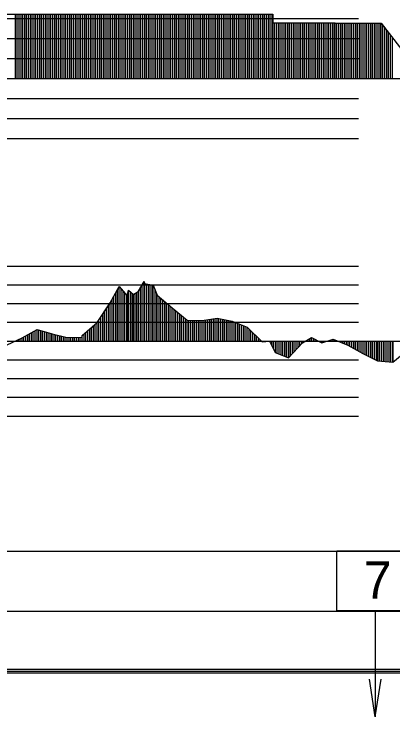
# Model space of a CAD drawing. Extents: x 2 to 10148, y 0 to 380.
# Drawn here: x 3622 to 3672.6, y 191.9 to 285.6 of the extents above; entities that cross this region are included whole.
import ezdxf

# ---------------------------------------------------------------- set-up
doc = ezdxf.new("R2010")
doc.units = 0
for name, color, linetype in [('POSUN_CARA', 7, 'Continuous'), ('POSUN_RASTR', 7, 'Continuous'), ('RYCHL_RASTR', 7, 'Continuous'), ('SLOUPEC', 7, 'Continuous'), ('ZRYCHL_CARA', 7, 'Continuous'), ('ZRYCHL_RASTR', 7, 'Continuous')]:
    doc.layers.add(name, color=color, linetype=linetype)

msp = doc.modelspace()

# ---------------------------------------------------------------- linework, layer by layer
at = {"layer": 'POSUN_CARA'}
for p, q in [((3638.631, 248.668), (3639.39, 249.956)), ((3639.131, 242), (3639.131, 249.517)), ((3639.381, 242), (3639.381, 249.942)), ((3639.39, 249.956), (3639.446, 249.679)), ((3639.39, 242), (3639.39, 249.956)), ((3639.446, 249.679), (3640.584, 249.465)), ((3639.446, 242), (3639.446, 249.679)), ((3639.696, 242), (3639.696, 249.632)), ((3639.946, 242), (3639.946, 249.585)), ((3640.196, 242), (3640.196, 249.538)), ((3640.446, 242), (3640.446, 249.491)), ((3640.584, 249.465), (3641.12, 248.129)), ((3640.584, 242), (3640.584, 249.465)), ((3634.848, 247.075), (3636.067, 249.276)), ((3635.598, 242), (3635.598, 248.429)), ((3635.848, 242), (3635.848, 248.88)), ((3636.067, 249.276), (3637.129, 248.042)), ((3636.067, 242), (3636.067, 249.276)), ((3636.317, 242), (3636.317, 248.986)), ((3636.567, 242), (3636.567, 248.695)), ((3636.817, 242), (3636.817, 248.405)), ((3637.129, 248.042), (3637.304, 248.785)), ((3637.304, 248.785), (3637.95, 248.221)), ((3637.304, 242), (3637.304, 248.785)), ((3637.554, 242), (3637.554, 248.567)), ((3637.804, 242), (3637.804, 248.349)), ((3637.95, 248.221), (3638.631, 248.668)), ((3638.2, 242), (3638.2, 248.385)), ((3638.394, 242), (3638.4, 248.516)), ((3638.631, 242), (3638.631, 248.668)), ((3638.881, 242), (3638.881, 249.093)), ((3640.834, 242), (3640.834, 248.842)), ((3635.098, 242), (3635.098, 247.526)), ((3635.348, 242), (3635.348, 247.977)), ((3637.067, 242), (3637.067, 248.114)), ((3637.129, 242), (3637.129, 248.042)), ((3637.95, 242), (3637.95, 248.221)), ((3641.084, 242), (3641.084, 248.219)), ((3641.12, 248.129), (3643.129, 246.413)), ((3641.12, 242), (3641.12, 248.129)), ((3641.37, 242), (3641.37, 247.916)), ((3641.62, 242), (3641.62, 247.702)), ((3641.87, 242), (3641.87, 247.489)), ((3633.105, 244.463), (3634.848, 247.075)), ((3634.605, 242), (3634.605, 246.711)), ((3634.848, 242), (3634.848, 247.075)), ((3642.12, 242), (3642.12, 247.275)), ((3642.37, 242), (3642.37, 247.062)), ((3642.62, 242), (3642.62, 246.848)), ((3642.87, 242), (3642.87, 246.634)), ((3633.855, 242), (3633.855, 245.587)), ((3634.105, 242), (3634.105, 245.961)), ((3634.355, 242), (3634.355, 246.336)), ((3643.12, 242), (3643.12, 246.421)), ((3643.129, 246.413), (3645.115, 244.77)), ((3643.129, 242), (3643.129, 246.413)), ((3643.379, 242), (3643.379, 246.206)), ((3643.629, 242), (3643.629, 245.999)), ((3643.879, 242), (3643.879, 245.792)), ((3644.129, 242), (3644.129, 245.585)), ((3633.355, 242), (3633.355, 244.837)), ((3633.605, 242), (3633.605, 245.212)), ((3644.379, 242), (3644.379, 245.379)), ((3644.629, 242), (3644.629, 245.172)), ((3644.879, 242), (3644.879, 244.965)), ((3645.115, 244.77), (3647.127, 244.736)), ((3645.115, 242), (3645.115, 244.77)), ((3645.365, 242), (3645.365, 244.766)), ((3645.615, 242), (3645.615, 244.762)), ((3645.865, 242), (3645.865, 244.758)), ((3646.115, 242), (3646.115, 244.753)), ((3646.365, 242), (3646.365, 244.749)), ((3646.615, 242), (3646.615, 244.745)), ((3646.865, 242), (3646.865, 244.741)), ((3647.115, 242), (3647.115, 244.736)), ((3647.127, 244.736), (3649.111, 245.038)), ((3647.127, 242), (3647.127, 244.736)), ((3647.377, 242), (3647.377, 244.774)), ((3647.627, 242), (3647.627, 244.812)), ((3647.877, 242), (3647.877, 244.85)), ((3648.127, 242), (3648.127, 244.889)), ((3648.377, 242), (3648.377, 244.927)), ((3648.627, 242), (3648.627, 244.965)), ((3648.877, 242), (3648.877, 245.003)), ((3649.111, 245.038), (3651.121, 244.656)), ((3649.111, 242), (3649.111, 245.038)), ((3649.361, 242), (3649.361, 244.991)), ((3649.611, 242), (3649.611, 244.943)), ((3649.861, 242), (3649.861, 244.896)), ((3650.111, 242), (3650.111, 244.848)), ((3650.361, 242), (3650.361, 244.8)), ((3650.611, 242), (3650.611, 244.753)), ((3650.861, 242), (3650.861, 244.705)), ((3651.111, 242), (3651.111, 244.658)), ((3651.121, 244.656), (3653.128, 243.837)), ((3651.121, 242), (3651.121, 244.656)), ((3631.116, 242.725), (3633.105, 244.463)), ((3632.366, 242), (3632.366, 243.817)), ((3632.616, 242), (3632.616, 244.036)), ((3632.866, 242), (3632.866, 244.254)), ((3633.105, 242), (3633.105, 244.463)), ((3651.371, 242), (3651.371, 244.554)), ((3651.621, 242), (3651.621, 244.452)), ((3651.871, 242), (3651.871, 244.35)), ((3652.121, 242), (3652.121, 244.248)), ((3652.371, 242), (3652.371, 244.146)), ((3652.621, 242), (3652.621, 244.044)), ((3652.871, 242), (3652.871, 243.942)), ((3653.121, 242), (3653.121, 243.84)), ((3653.128, 243.837), (3655.125, 241.916)), ((3653.128, 242), (3653.128, 243.837)), ((3623.098, 242.411), (3625.089, 243.532)), ((3623.848, 242), (3623.848, 242.833)), ((3624.098, 242), (3624.098, 242.974)), ((3624.348, 242), (3624.348, 243.115)), ((3624.598, 242), (3624.598, 243.256)), ((3624.848, 242), (3624.848, 243.396)), ((3625.089, 243.532), (3627.116, 242.977)), ((3625.089, 242), (3625.089, 243.532)), ((3625.339, 242), (3625.339, 243.463)), ((3625.589, 242), (3625.589, 243.395)), ((3625.839, 242), (3625.839, 243.326)), ((3626.089, 242), (3626.089, 243.258)), ((3626.339, 242), (3626.339, 243.19)), ((3626.589, 242), (3626.589, 243.121)), ((3626.839, 242), (3626.839, 243.053)), ((3627.089, 242), (3627.089, 242.984)), ((3627.116, 242.977), (3629.112, 242.477)), ((3627.116, 242), (3627.116, 242.977)), ((3627.366, 242), (3627.366, 242.914)), ((3627.616, 242), (3627.616, 242.852)), ((3627.866, 242), (3627.866, 242.789)), ((3628.116, 242), (3628.116, 242.726)), ((3631.105, 242.514), (3631.116, 242.725)), ((3631.116, 242), (3631.116, 242.725)), ((3631.366, 242), (3631.366, 242.944)), ((3631.616, 242), (3631.616, 243.162)), ((3631.866, 242), (3631.866, 243.381)), ((3632.116, 242), (3632.116, 243.599)), ((3653.378, 242), (3653.378, 243.597)), ((3653.628, 242), (3653.628, 243.356)), ((3653.878, 242), (3653.878, 243.116)), ((3654.128, 242), (3654.128, 242.875)), ((3621.098, 241.49), (3623.098, 242.411)), ((3622.098, 242), (3622.098, 241.951)), ((3622.348, 242), (3622.348, 242.066)), ((3622.598, 242), (3622.598, 242.181)), ((3622.848, 242), (3622.848, 242.296)), ((3623.098, 242), (3623.098, 242.411)), ((3623.098, 242), (3623.098, 242.411)), ((3623.348, 242), (3623.348, 242.552)), ((3623.598, 242), (3623.598, 242.693)), ((3628.366, 242), (3628.366, 242.664)), ((3628.616, 242), (3628.616, 242.601)), ((3628.866, 242), (3628.866, 242.539)), ((3629.112, 242.477), (3631.105, 242.514)), ((3629.112, 242), (3629.112, 242.477)), ((3629.362, 242), (3629.362, 242.482)), ((3629.612, 242), (3629.612, 242.486)), ((3629.862, 242), (3629.862, 242.491)), ((3630.112, 242), (3630.112, 242.496)), ((3630.362, 242), (3630.362, 242.5)), ((3630.612, 242), (3630.612, 242.505)), ((3630.862, 242), (3630.862, 242.51)), ((3631.105, 242), (3631.105, 242.514)), ((3654.378, 242), (3654.378, 242.635)), ((3654.628, 242), (3654.628, 242.394)), ((3654.878, 242), (3654.878, 242.154)), ((3655.125, 241.916), (3656.108, 242.001)), ((3655.125, 242), (3655.125, 241.916)), ((3655.375, 242), (3655.375, 241.938)), ((3655.625, 242), (3655.625, 241.959)), ((3655.875, 242), (3655.875, 241.981)), ((3656.108, 242.001), (3656.85, 240.468)), ((3656.108, 242), (3656.108, 242.001)), ((3656.358, 242), (3656.358, 241.484)), ((3656.608, 242), (3656.608, 240.968)), ((3656.85, 242), (3656.85, 240.468)), ((3657.1, 242), (3657.1, 240.366)), ((3657.35, 242), (3657.35, 240.264)), ((3657.6, 242), (3657.6, 240.162)), ((3657.85, 242), (3657.85, 240.06)), ((3658.1, 242), (3658.1, 239.959)), ((3658.35, 242), (3658.35, 239.857)), ((3658.6, 242), (3658.6, 239.755)), ((3658.618, 242), (3658.618, 239.748)), ((3658.868, 242), (3658.868, 240.017)), ((3659.118, 242), (3659.118, 240.286)), ((3659.368, 242), (3659.368, 240.556)), ((3659.618, 242), (3659.618, 240.825)), ((3659.868, 242), (3659.868, 241.094)), ((3660.118, 242), (3660.118, 241.364)), ((3660.368, 242), (3660.368, 241.633)), ((3660.503, 241.778), (3661.708, 242.475)), ((3660.503, 242), (3660.503, 241.778)), ((3660.753, 242), (3660.753, 241.923)), ((3661.003, 242), (3661.003, 242.067)), ((3661.253, 242), (3661.253, 242.212)), ((3661.503, 242), (3661.503, 242.356)), ((3661.708, 242.475), (3663.097, 241.755)), ((3661.708, 242), (3661.708, 242.475)), ((3661.958, 242), (3661.958, 242.345)), ((3662.208, 242), (3662.208, 242.216)), ((3662.458, 242), (3662.458, 242.086)), ((3662.708, 242), (3662.708, 241.957)), ((3662.958, 242), (3662.958, 241.827)), ((3663.097, 241.755), (3664.585, 242.232)), ((3663.097, 242), (3663.097, 241.755)), ((3663.347, 242), (3663.347, 241.835)), ((3663.597, 242), (3663.597, 241.915)), ((3663.847, 242), (3663.847, 241.995)), ((3664.097, 242), (3664.097, 242.075)), ((3664.347, 242), (3664.347, 242.155)), ((3664.585, 242.232), (3666.543, 241.434)), ((3664.585, 242), (3664.585, 242.232)), ((3664.835, 242), (3664.835, 242.13)), ((3665.085, 242), (3665.085, 242.028)), ((3665.335, 242), (3665.335, 241.926)), ((3665.585, 242), (3665.585, 241.824)), ((3665.835, 242), (3665.835, 241.723)), ((3666.085, 242), (3666.085, 241.621)), ((3666.335, 242), (3666.335, 241.519)), ((3666.543, 242), (3666.543, 241.434)), ((3666.793, 242), (3666.793, 241.301)), ((3667.043, 242), (3667.043, 241.168)), ((3667.293, 242), (3667.293, 241.034)), ((3667.543, 242), (3667.543, 240.901)), ((3667.793, 242), (3667.793, 240.768)), ((3668.043, 242), (3668.043, 240.634)), ((3668.293, 242), (3668.293, 240.501)), ((3668.543, 242), (3668.543, 240.368)), ((3668.565, 242), (3668.565, 240.356)), ((3668.815, 242), (3668.815, 240.227)), ((3669.065, 242), (3669.065, 240.097)), ((3669.315, 242), (3669.315, 239.968)), ((3669.565, 242), (3669.565, 239.838)), ((3669.815, 242), (3669.815, 239.709)), ((3670.065, 242), (3670.065, 239.58)), ((3670.315, 242), (3670.315, 239.45)), ((3670.507, 242), (3670.507, 239.351)), ((3670.757, 242), (3670.757, 239.331)), ((3671.007, 242), (3671.007, 239.312)), ((3671.257, 242), (3671.257, 239.292)), ((3671.507, 242), (3671.507, 239.273)), ((3671.757, 242), (3671.757, 239.253)), ((3672.007, 242), (3672.007, 239.234)), ((3672.257, 242), (3672.257, 239.214)), ((3672.507, 242), (3672.507, 239.194)), ((3672.542, 242), (3672.542, 239.192)), ((3658.618, 239.748), (3660.503, 241.778)), ((3666.543, 241.434), (3668.565, 240.356)), ((3656.85, 240.468), (3658.618, 239.748)), ((3668.565, 240.356), (3670.507, 239.351)), ((3672.542, 239.192), (3674.539, 240.84)), ((3670.507, 239.351), (3672.542, 239.192))]:
    msp.add_line(p, q, dxfattribs=at)
at = {"layer": 'POSUN_RASTR'}
for p, q in [((3479.383, 252), (3668, 252)), ((3479.475, 249.5), (3668, 249.5)), ((3479.567, 247), (3668, 247)), ((3479.767, 244.5), (3668, 244.5)), ((3155.54, 242), (4045.764, 242)), ((3472, 239.5), (3668, 239.5)), ((3472, 237), (3668, 237)), ((3472, 234.5), (3668, 234.5)), ((3472, 232), (3668, 232))]:
    msp.add_line(p, q, dxfattribs=at)
at = {"layer": 'RYCHL_RASTR'}
for p, q in [((3155.54, 214), (4046.979, 214)), ((3155.54, 206), (4046.951, 206)), ((3155.54, 198.25), (4046.943, 198.25)), ((3155.54, 198), (4046.933, 198)), ((3155.54, 197.75), (4046.924, 197.75))]:
    msp.add_line(p, q, dxfattribs=at)
at = {"layer": 'SLOUPEC'}
for p, q in [((3670.224, 206.034), (3670.224, 191.884)), ((3670.224, 191.884), (3669.456, 196.926)), ((3670.224, 191.884), (3670.991, 196.926))]:
    msp.add_line(p, q, dxfattribs=at)
msp.add_lwpolyline([(3665.078, 214.033), (3675.37, 214.033), (3675.37, 206.034), (3665.078, 206.034)], close=True, dxfattribs=at)
at = {"layer": 'ZRYCHL_CARA'}
for p, q in [((3615.454, 285.597), (3656.542, 285.597)), ((3622.204, 277), (3622.204, 285.597)), ((3622.454, 277), (3622.454, 285.597)), ((3622.704, 277), (3622.704, 285.597)), ((3622.954, 277), (3622.954, 285.597)), ((3623.204, 277), (3623.204, 285.597)), ((3623.454, 277), (3623.454, 285.597)), ((3623.704, 277), (3623.704, 285.597)), ((3623.954, 277), (3623.954, 285.597)), ((3624.204, 277), (3624.204, 285.597)), ((3624.454, 277), (3624.454, 285.597)), ((3624.704, 277), (3624.704, 285.597)), ((3624.954, 277), (3624.954, 285.597)), ((3625.204, 277), (3625.204, 285.597)), ((3625.454, 277), (3625.454, 285.597)), ((3625.704, 277), (3625.704, 285.597)), ((3625.954, 277), (3625.954, 285.597)), ((3626.204, 277), (3626.204, 285.597)), ((3626.454, 277), (3626.454, 285.597)), ((3626.704, 277), (3626.704, 285.597)), ((3626.954, 277), (3626.954, 285.597)), ((3627.204, 277), (3627.204, 285.597)), ((3627.454, 277), (3627.454, 285.597)), ((3627.704, 277), (3627.704, 285.597)), ((3627.954, 277), (3627.954, 285.597)), ((3628.204, 277), (3628.204, 285.597)), ((3628.454, 277), (3628.454, 285.597)), ((3628.704, 277), (3628.704, 285.597)), ((3628.954, 277), (3628.954, 285.597)), ((3629.204, 277), (3629.204, 285.597)), ((3629.454, 277), (3629.454, 285.597)), ((3629.704, 277), (3629.704, 285.597)), ((3629.954, 277), (3629.954, 285.597)), ((3630.204, 277), (3630.204, 285.597)), ((3630.454, 277), (3630.454, 285.597)), ((3630.704, 277), (3630.704, 285.597)), ((3630.954, 277), (3630.954, 285.597)), ((3631.204, 277), (3631.204, 285.597)), ((3631.454, 277), (3631.454, 285.597)), ((3631.704, 277), (3631.704, 285.597)), ((3631.954, 277), (3631.954, 285.597)), ((3632.204, 277), (3632.204, 285.597)), ((3632.454, 277), (3632.454, 285.597)), ((3632.704, 277), (3632.704, 285.597)), ((3632.954, 277), (3632.954, 285.597)), ((3633.204, 277), (3633.204, 285.597)), ((3633.454, 277), (3633.454, 285.597)), ((3633.704, 277), (3633.704, 285.597)), ((3633.954, 277), (3633.954, 285.597)), ((3634.204, 277), (3634.204, 285.597)), ((3634.454, 277), (3634.454, 285.597)), ((3634.704, 277), (3634.704, 285.597)), ((3634.954, 277), (3634.954, 285.597)), ((3635.204, 277), (3635.204, 285.597)), ((3635.454, 277), (3635.454, 285.597)), ((3635.704, 277), (3635.704, 285.597)), ((3635.954, 277), (3635.954, 285.597)), ((3636.204, 277), (3636.204, 285.597)), ((3636.454, 277), (3636.454, 285.597)), ((3636.704, 277), (3636.704, 285.597)), ((3636.954, 277), (3636.954, 285.597)), ((3637.204, 277), (3637.204, 285.597)), ((3637.454, 277), (3637.454, 285.597)), ((3637.704, 277), (3637.704, 285.597)), ((3637.954, 277), (3637.954, 285.597)), ((3638.204, 277), (3638.204, 285.597)), ((3638.454, 277), (3638.454, 285.597)), ((3638.704, 277), (3638.704, 285.597)), ((3638.954, 277), (3638.954, 285.597)), ((3639.204, 277), (3639.204, 285.597)), ((3639.454, 277), (3639.454, 285.597)), ((3639.704, 277), (3639.704, 285.597)), ((3639.954, 277), (3639.954, 285.597)), ((3640.204, 277), (3640.204, 285.597)), ((3640.454, 277), (3640.454, 285.597)), ((3640.704, 277), (3640.704, 285.597)), ((3640.954, 277), (3640.954, 285.597)), ((3641.204, 277), (3641.204, 285.597)), ((3641.454, 277), (3641.454, 285.597)), ((3641.704, 277), (3641.704, 285.597)), ((3641.954, 277), (3641.954, 285.597)), ((3642.204, 277), (3642.204, 285.597)), ((3642.454, 277), (3642.454, 285.597)), ((3642.704, 277), (3642.704, 285.597)), ((3642.954, 277), (3642.954, 285.597)), ((3643.204, 277), (3643.204, 285.597)), ((3643.454, 277), (3643.454, 285.597)), ((3643.704, 277), (3643.704, 285.597)), ((3643.954, 277), (3643.954, 285.597)), ((3644.204, 277), (3644.204, 285.597)), ((3644.454, 277), (3644.454, 285.597)), ((3644.704, 277), (3644.704, 285.597)), ((3644.954, 277), (3644.954, 285.597)), ((3645.204, 277), (3645.204, 285.597)), ((3645.454, 277), (3645.454, 285.597)), ((3645.704, 277), (3645.704, 285.597)), ((3645.954, 277), (3645.954, 285.597)), ((3646.204, 277), (3646.204, 285.597)), ((3646.454, 277), (3646.454, 285.597)), ((3646.704, 277), (3646.704, 285.597)), ((3646.954, 277), (3646.954, 285.597)), ((3647.204, 277), (3647.204, 285.597)), ((3647.454, 277), (3647.454, 285.597)), ((3647.704, 277), (3647.704, 285.597)), ((3647.954, 277), (3647.954, 285.597)), ((3648.204, 277), (3648.204, 285.597)), ((3648.454, 277), (3648.454, 285.597)), ((3648.704, 277), (3648.704, 285.597)), ((3648.954, 277), (3648.954, 285.597)), ((3649.204, 277), (3649.204, 285.597)), ((3649.454, 277), (3649.454, 285.597)), ((3649.704, 277), (3649.704, 285.597)), ((3649.954, 277), (3649.954, 285.597)), ((3650.204, 277), (3650.204, 285.597)), ((3650.454, 277), (3650.454, 285.597)), ((3650.704, 277), (3650.704, 285.597)), ((3650.954, 277), (3650.954, 285.597)), ((3651.204, 277), (3651.204, 285.597)), ((3651.454, 277), (3651.454, 285.597)), ((3651.704, 277), (3651.704, 285.597)), ((3651.954, 277), (3651.954, 285.597)), ((3652.204, 277), (3652.204, 285.597)), ((3652.454, 277), (3652.454, 285.597)), ((3652.704, 277), (3652.704, 285.597)), ((3652.954, 277), (3652.954, 285.597)), ((3653.204, 277), (3653.204, 285.597)), ((3653.454, 277), (3653.454, 285.597)), ((3653.704, 277), (3653.704, 285.597)), ((3653.954, 277), (3653.954, 285.597)), ((3654.204, 277), (3654.204, 285.597)), ((3654.454, 277), (3654.454, 285.597)), ((3654.704, 277), (3654.704, 285.597)), ((3654.954, 277), (3654.954, 285.597)), ((3655.204, 277), (3655.204, 285.597)), ((3655.454, 277), (3655.454, 285.597)), ((3655.704, 277), (3655.704, 285.597)), ((3655.954, 277), (3655.954, 285.597)), ((3656.204, 277), (3656.204, 285.597)), ((3656.454, 277), (3656.454, 285.597)), ((3656.542, 285.597), (3656.542, 284.422)), ((3656.542, 277), (3656.542, 284.422)), ((3656.542, 284.422), (3664.855, 284.422)), ((3656.792, 277), (3656.792, 284.422)), ((3657.042, 277), (3657.042, 284.422)), ((3657.292, 277), (3657.292, 284.422)), ((3657.542, 277), (3657.542, 284.422)), ((3657.792, 277), (3657.792, 284.422)), ((3658.042, 277), (3658.042, 284.422)), ((3658.292, 277), (3658.292, 284.422)), ((3658.542, 277), (3658.542, 284.422)), ((3658.792, 277), (3658.792, 284.422)), ((3659.042, 277), (3659.042, 284.422)), ((3659.292, 277), (3659.292, 284.422)), ((3659.542, 277), (3659.542, 284.422)), ((3659.792, 277), (3659.792, 284.422)), ((3660.042, 277), (3660.042, 284.422)), ((3660.292, 277), (3660.292, 284.422)), ((3660.542, 277), (3660.542, 284.422)), ((3660.792, 277), (3660.792, 284.422)), ((3661.042, 277), (3661.042, 284.422)), ((3661.292, 277), (3661.292, 284.422)), ((3661.542, 277), (3661.542, 284.422)), ((3661.792, 277), (3661.792, 284.422)), ((3662.042, 277), (3662.042, 284.422)), ((3662.292, 277), (3662.292, 284.422)), ((3662.542, 277), (3662.542, 284.422)), ((3662.792, 277), (3662.792, 284.422)), ((3663.042, 277), (3663.042, 284.422)), ((3663.292, 277), (3663.292, 284.422)), ((3663.542, 277), (3663.542, 284.422)), ((3663.792, 277), (3663.792, 284.422)), ((3664.042, 277), (3664.042, 284.422)), ((3664.292, 277), (3664.292, 284.422)), ((3664.542, 277), (3664.542, 284.422)), ((3664.792, 277), (3664.792, 284.422)), ((3664.855, 284.422), (3664.855, 284.382)), ((3664.855, 277), (3664.855, 284.382)), ((3664.855, 284.382), (3670.996, 284.382)), ((3665.105, 277), (3665.105, 284.382)), ((3665.355, 277), (3665.355, 284.382)), ((3665.605, 277), (3665.605, 284.382)), ((3665.855, 277), (3665.855, 284.382)), ((3666.105, 277), (3666.105, 284.382)), ((3666.355, 277), (3666.355, 284.382)), ((3666.605, 277), (3666.605, 284.382)), ((3666.855, 277), (3666.855, 284.382)), ((3667.105, 277), (3667.105, 284.382)), ((3667.355, 277), (3667.355, 284.382)), ((3667.605, 277), (3667.605, 284.382)), ((3667.855, 277), (3667.855, 284.382)), ((3668.105, 277), (3668.105, 284.382)), ((3668.355, 277), (3668.355, 284.382)), ((3668.605, 277), (3668.605, 284.382)), ((3668.855, 277), (3668.855, 284.382)), ((3669.105, 277), (3669.105, 284.382)), ((3669.355, 277), (3669.355, 284.382)), ((3669.605, 277), (3669.605, 284.382)), ((3669.855, 277), (3669.855, 284.382)), ((3670.105, 277), (3670.105, 284.382)), ((3670.355, 277), (3670.355, 284.382)), ((3670.605, 277), (3670.605, 284.382)), ((3670.855, 277), (3670.855, 284.382)), ((3670.996, 277), (3670.996, 284.382)), ((3670.996, 284.382), (3676.696, 277)), ((3671.246, 277), (3671.246, 284.058)), ((3671.496, 277), (3671.496, 283.734)), ((3671.746, 277), (3671.746, 283.411)), ((3671.996, 277), (3671.996, 283.087)), ((3672.246, 277), (3672.246, 282.763)), ((3672.496, 277), (3672.496, 282.439)), ((3155.54, 277), (4045.764, 277))]:
    msp.add_line(p, q, dxfattribs=at)
at = {"layer": 'ZRYCHL_RASTR'}
for p, q in [((3472, 285), (3668, 285)), ((3472, 282.333), (3668, 282.333)), ((3472, 279.667), (3668, 279.667)), ((3458, 274.333), (3668, 274.333)), ((3458, 271.667), (3668, 271.667)), ((3458, 269), (3668, 269))]:
    msp.add_line(p, q, dxfattribs=at)

# ---------------------------------------------------------------- texts
at = {"layer": 'SLOUPEC'}
msp.add_text('7', height=5, dxfattribs=at).set_placement((3668.678, 207.652))

doc.saveas('drawing.dxf')
